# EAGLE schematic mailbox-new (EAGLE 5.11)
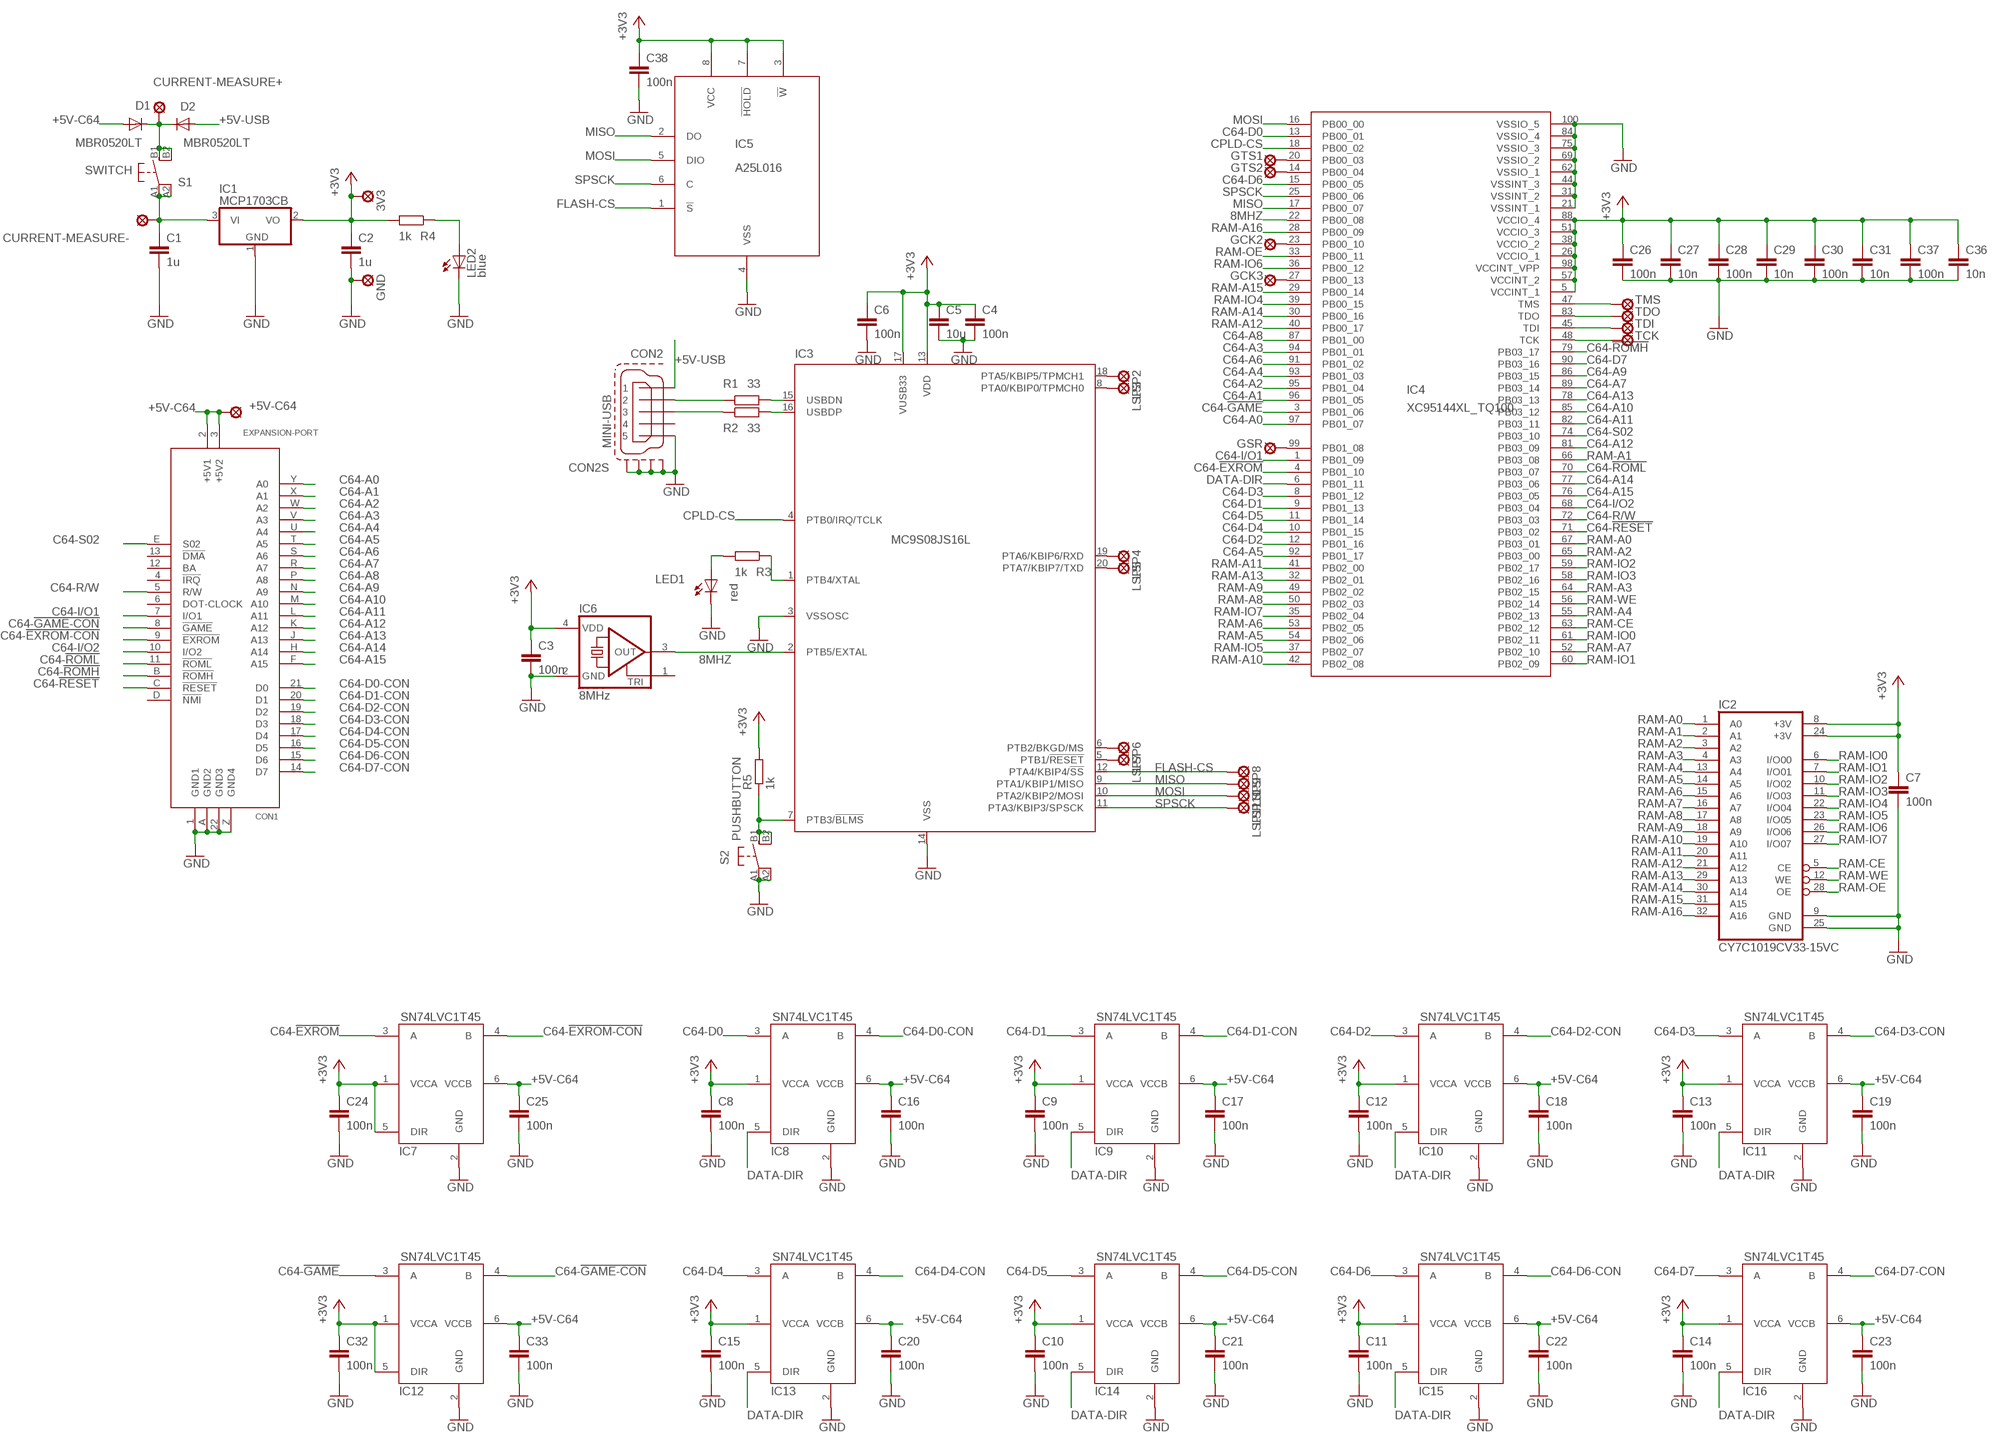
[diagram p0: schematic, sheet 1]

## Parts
3V3  LSP10  [LSP10]
+5V-C64  LSP10  [LSP10]
C1  1u  C-EUC1210  [C1210]
C2  1u  C-EUC1210  [C1210]
C3  100n  C-EUC0603  [C0603]
C4  100n  C-EUC0603  [C0603]
C5  10u  C-EUC1210  [C1210]
C6  100n  C-EUC0603  [C0603]
C7  100n  C-EUC0603  [C0603]
C8  100n  C-EUC0603  [C0603]
C9  100n  C-EUC0603  [C0603]
C10  100n  C-EUC0603  [C0603]
C11  100n  C-EUC0603  [C0603]
C12  100n  C-EUC0603  [C0603]
C13  100n  C-EUC0603  [C0603]
C14  100n  C-EUC0603  [C0603]
C15  100n  C-EUC0603  [C0603]
C16  100n  C-EUC0603  [C0603]
C17  100n  C-EUC0603  [C0603]
C18  100n  C-EUC0603  [C0603]
C19  100n  C-EUC0603  [C0603]
C20  100n  C-EUC0603  [C0603]
C21  100n  C-EUC0603  [C0603]
C22  100n  C-EUC0603  [C0603]
C23  100n  C-EUC0603  [C0603]
C24  100n  C-EUC0603  [C0603]
C25  100n  C-EUC0603  [C0603]
C26  100n  C-EUC0603  [C0603]
C27  10n  C-EUC0603  [C0603]
C28  100n  C-EUC0603  [C0603]
C29  10n  C-EUC0603  [C0603]
C30  100n  C-EUC0603  [C0603]
C31  10n  C-EUC0603  [C0603]
C32  100n  C-EUC0603  [C0603]
C33  100n  C-EUC0603  [C0603]
C36  10n  C-EUC0603  [C0603]
C37  100n  C-EUC0603  [C0603]
C38  100n  C-EUC0603  [C0603]
CON1  EXPANSION-PORT  [EXPANSION-PORT]
CON2  MINI-USB  MINI-USB-SHIELD-UX60-MB-5ST  [TYCO]
CURRENT-MEASURE+  LSP10  [LSP10]
CURRENT-MEASURE-  LSP10  [LSP10]
D1  MBR0520LT  [SOD123]
D2  MBR0520LT  [SOD123]
GCK2  LSP10  [LSP10]
GCK3  LSP10  [LSP10]
GND  LSP10  [LSP10]
GSR  LSP10  [LSP10]
GTS1  LSP10  [LSP10]
GTS2  LSP10  [LSP10]
IC1  MCP1703CB  [SOT23]
IC2  CY7C1019CV33-15VC  [SOJ32-400]
IC3  MC9S08JS16L  [SO-20DW]
IC4  XC95144XL_TQ100  XC9572XL_TQ100  [TQ100]
IC5  A25L016  [SOIC8]
IC6  8MHz  ASE  [ASE]
IC7  SN74LVC1T45  [SOT23-6]
IC8  SN74LVC1T45  [SOT23-6]
IC9  SN74LVC1T45  [SOT23-6]
IC10  SN74LVC1T45  [SOT23-6]
IC11  SN74LVC1T45  [SOT23-6]
IC12  SN74LVC1T45  [SOT23-6]
IC13  SN74LVC1T45  [SOT23-6]
IC14  SN74LVC1T45  [SOT23-6]
IC15  SN74LVC1T45  [SOT23-6]
IC16  SN74LVC1T45  [SOT23-6]
LED1  red  LED5MM  [LED5MM]
LED2  blue  LED5MM  [LED5MM]
LSP2  LSP10  [LSP10]
LSP3  LSP10  [LSP10]
LSP4  LSP10  [LSP10]
LSP5  LSP10  [LSP10]
LSP6  LSP10  [LSP10]
LSP7  LSP10  [LSP10]
LSP8  LSP10  [LSP10]
LSP9  LSP10  [LSP10]
LSP10  LSP10  [LSP10]
LSP11  LSP10  [LSP10]
R1  33  R-EU_R0805  [R0805]
R2  33  R-EU_R0805  [R0805]
R3  1k  R-EU_R0805  [R0805]
R4  1k  R-EU_R0805  [R0805]
R5  1k  R-EU_R0805  [R0805]
S1  SWITCH  [SWITCH]
S2  PUSHBUTTON  [PUSHBUTTON]
TCK  LSP10  [LSP10]
TDI  LSP10  [LSP10]
TDO  LSP10  [LSP10]
TMS  LSP10  [LSP10]

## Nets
8MHZ: IC3.2(PTB5/EXTAL) IC4.22(PB00_08) IC6.3(OUT)
+3V3: 3V3.MP C2.1 C3.1 C4.1 C5.1 C6.1 C7.1 C8.1 C9.1 C10.1 C11.1 C12.1 C13.1 C14.1 C15.1 C24.1 C26.1 C27.1 C28.1 C29.1 C30.1 C31.1 C32.1 C36.1 C37.1 C38.1 IC1.2(VO) IC2.8(+3V) IC2.24(+3V) IC3.13(VDD) IC3.17(VUSB33) IC4.5(VCCINT_1) IC4.26(VCCIO_1) IC4.38(VCCIO_2) IC4.51(VCCIO_3) IC4.57(VCCINT_2) IC4.88(VCCIO_4) IC4.98(VCCINT_VPP) IC5.3(!W) IC5.7(!HOLD) IC5.8(VCC) IC6.4(VDD) IC7.1(VCCA) IC7.5(DIR) IC8.1(VCCA) IC9.1(VCCA) IC10.1(VCCA) IC11.1(VCCA) IC12.1(VCCA) IC12.5(DIR) IC13.1(VCCA) IC14.1(VCCA) IC15.1(VCCA) IC16.1(VCCA) R4.2 R5.2
+5V-C64: +5V-C64.MP C16.1 C17.1 C18.1 C19.1 C20.1 C21.1 C22.1 C23.1 C25.1 C33.1 CON1.2(+5V1) CON1.3(+5V2) D1.A IC7.6(VCCB) IC8.6(VCCB) IC9.6(VCCB) IC10.6(VCCB) IC11.6(VCCB) IC12.6(VCCB) IC13.6(VCCB) IC14.6(VCCB) IC15.6(VCCB) IC16.6(VCCB)
+5V-USB: CON2.1 D2.A
C64-!EXROM: IC4.4(PB01_10) IC7.3(A)
C64-!EXROM-CON: CON1.9(!EXROM) IC7.4(B)
C64-!GAME: IC4.3(PB01_06) IC12.3(A)
C64-!GAME-CON: CON1.8(!GAME) IC12.4(B)
C64-!RESET: CON1.C(!RESET) IC4.71(PB03_02)
C64-!ROMH: CON1.B(!ROMH) IC4.79(PB03_17)
C64-!ROML: CON1.11(!ROML) IC4.70(PB03_07)
C64-A0: CON1.Y(A0) IC4.97(PB01_07)
C64-A1: CON1.X(A1) IC4.96(PB01_05)
C64-A2: CON1.W(A2) IC4.95(PB01_04)
C64-A3: CON1.V(A3) IC4.94(PB01_01)
C64-A4: CON1.U(A4) IC4.93(PB01_03)
C64-A5: CON1.T(A5) IC4.92(PB01_17)
C64-A6: CON1.S(A6) IC4.91(PB01_02)
C64-A7: CON1.R(A7) IC4.89(PB03_14)
C64-A8: CON1.P(A8) IC4.87(PB01_00)
C64-A9: CON1.N(A9) IC4.86(PB03_15)
C64-A10: CON1.M(A10) IC4.85(PB03_12)
C64-A11: CON1.L(A11) IC4.82(PB03_11)
C64-A12: CON1.K(A12) IC4.81(PB03_09)
C64-A13: CON1.J(A13) IC4.78(PB03_13)
C64-A14: CON1.H(A14) IC4.77(PB03_06)
C64-A15: CON1.F(A15) IC4.76(PB03_05)
C64-D0: IC4.13(PB00_01) IC8.3(A)
C64-D0-CON: CON1.21(D0) IC8.4(B)
C64-D1: IC4.9(PB01_13) IC9.3(A)
C64-D1-CON: CON1.20(D1) IC9.4(B)
C64-D2: IC4.12(PB01_16) IC10.3(A)
C64-D2-CON: CON1.19(D2) IC10.4(B)
C64-D3: IC4.8(PB01_12) IC11.3(A)
C64-D3-CON: CON1.18(D3) IC11.4(B)
C64-D4: IC4.10(PB01_15) IC13.3(A)
C64-D4-CON: CON1.17(D4) IC13.4(B)
C64-D5: IC4.11(PB01_14) IC14.3(A)
C64-D5-CON: CON1.16(D5) IC14.4(B)
C64-D6: IC4.15(PB00_05) IC15.3(A)
C64-D6-CON: CON1.15(D6) IC15.4(B)
C64-D7: IC4.90(PB03_16) IC16.3(A)
C64-D7-CON: CON1.14(D7) IC16.4(B)
C64-I/O1: CON1.7(I/O1) IC4.1(PB01_09)
C64-I/O2: CON1.10(I/O2) IC4.68(PB03_04)
C64-R/W: CON1.5(R/W) IC4.72(PB03_03)
C64-S02: CON1.E(S02) IC4.74(PB03_10)
CPLD-CS: IC3.4(PTB0/IRQ/TCLK) IC4.18(PB00_02)
DATA-DIR: IC4.6(PB01_11) IC8.5(DIR) IC9.5(DIR) IC10.5(DIR) IC11.5(DIR) IC13.5(DIR) IC14.5(DIR) IC15.5(DIR) IC16.5(DIR)
FLASH-CS: IC3.12(PTA4/KBIP4/!SS) IC5.1(!S) LSP8.MP
GND: C1.2 C2.2 C3.2 C4.2 C5.2 C6.2 C7.2 C8.2 C9.2 C10.2 C11.2 C12.2 C13.2 C14.2 C15.2 C16.2 C17.2 C18.2 C19.2 C20.2 C21.2 C22.2 C23.2 C24.2 C25.2 C26.2 C27.2 C28.2 C29.2 C30.2 C31.2 C32.2 C33.2 C36.2 C37.2 C38.2 CON1.1(GND1) CON1.22(GND3) CON1.A(GND2) CON1.Z(GND4) CON2.5 CON2.M1(S1) CON2.M2(S2) CON2.M3(S3) CON2.M4(S4) GND.MP IC1.1(GND) IC2.9(GND) IC2.25(GND) IC3.3(VSSOSC) IC3.14(VSS) IC4.21(VSSINT_1) IC4.31(VSSINT_2) IC4.44(VSSINT_3) IC4.62(VSSIO_1) IC4.69(VSSIO_2) IC4.75(VSSIO_3) IC4.84(VSSIO_4) IC4.100(VSSIO_5) IC5.4(VSS) IC6.2(GND) IC7.2(GND) IC8.2(GND) IC9.2(GND) IC10.2(GND) IC11.2(GND) IC12.2(GND) IC13.2(GND) IC14.2(GND) IC15.2(GND) IC16.2(GND) LED1.K(C) LED2.K(C) S2.A1(P) S2.A2(P1)
MISO: IC3.9(PTA1/KBIP1/MISO) IC4.17(PB00_07) IC5.2(DO) LSP9.MP
MOSI: IC3.10(PTA2/KBIP2/MOSI) IC4.16(PB00_00) IC5.5(DIO) LSP10.MP
N$1: CON2.2 R1.1
N$3: IC3.1(PTB4/XTAL) R3.1
N$4: LED2.A R4.1
N$5: C1.1 CURRENT-MEASURE-.MP IC1.3(VI) S1.A1(P) S1.A2(P1)
N$6: CON2.3 R2.1
N$7: IC3.15(USBDN) R1.2
N$8: IC3.16(USBDP) R2.2
N$9: LED1.A R3.2
N$10: CURRENT-MEASURE+.MP D1.C D2.C S1.B1(S) S1.B2(S1)
N$11: IC3.18(PTA5/KBIP5/TPMCH1) LSP2.MP
N$12: IC3.8(PTA0/KBIP0/TPMCH0) LSP3.MP
N$13: IC3.19(PTA6/KBIP6/RXD) LSP4.MP
N$14: IC3.20(PTA7/KBIP7/TXD) LSP5.MP
N$15: IC3.6(PTB2/BKGD/MS) LSP6.MP
N$16: IC3.5(PTB1/!RESET) LSP7.MP
N$18: GCK2.MP IC4.23(PB00_10)
N$19: GCK3.MP IC4.27(PB00_13)
N$20: GTS1.MP IC4.20(PB00_03)
N$21: GTS2.MP IC4.14(PB00_04)
N$22: GSR.MP IC4.99(PB01_08)
N$35: IC3.7(PTB3/!BLMS) R5.1 S2.B1(S) S2.B2(S1)
RAM-A0: IC2.1(A0) IC4.67(PB03_01)
RAM-A1: IC2.2(A1) IC4.66(PB03_08)
RAM-A2: IC2.3(A2) IC4.65(PB03_00)
RAM-A3: IC2.4(A3) IC4.64(PB02_15)
RAM-A4: IC2.13(A4) IC4.55(PB02_13)
RAM-A5: IC2.14(A5) IC4.54(PB02_06)
RAM-A6: IC2.15(A6) IC4.53(PB02_05)
RAM-A7: IC2.16(A7) IC4.52(PB02_10)
RAM-A8: IC2.17(A8) IC4.50(PB02_03)
RAM-A9: IC2.18(A9) IC4.49(PB02_02)
RAM-A10: IC2.19(A10) IC4.42(PB02_08)
RAM-A11: IC2.20(A11) IC4.41(PB02_00)
RAM-A12: IC2.21(A12) IC4.40(PB00_17)
RAM-A13: IC2.29(A13) IC4.32(PB02_01)
RAM-A14: IC2.30(A14) IC4.30(PB00_16)
RAM-A15: IC2.31(A15) IC4.29(PB00_14)
RAM-A16: IC2.32(A16) IC4.28(PB00_09)
RAM-CE: IC2.5(CE) IC4.63(PB02_12)
RAM-IO0: IC2.6(I/O00) IC4.61(PB02_11)
RAM-IO1: IC2.7(I/O01) IC4.60(PB02_09)
RAM-IO2: IC2.10(I/O02) IC4.59(PB02_17)
RAM-IO3: IC2.11(I/O03) IC4.58(PB02_16)
RAM-IO4: IC2.22(I/O04) IC4.39(PB00_15)
RAM-IO5: IC2.23(I/O05) IC4.37(PB02_07)
RAM-IO6: IC2.26(I/O06) IC4.36(PB00_12)
RAM-IO7: IC2.27(I/O07) IC4.35(PB02_04)
RAM-OE: IC2.28(OE) IC4.33(PB00_11)
RAM-WE: IC2.12(WE) IC4.56(PB02_14)
SPSCK: IC3.11(PTA3/KBIP3/SPSCK) IC4.25(PB00_06) IC5.6(C) LSP11.MP
TCK: IC4.48(TCK) TCK.MP
TDI: IC4.45(TDI) TDI.MP
TDO: IC4.83(TDO) TDO.MP
TMS: IC4.47(TMS) TMS.MP
Unconnected: CON1.4(!IRQ) CON1.6(DOT-CLOCK) CON1.12(BA) CON1.13(!DMA) CON1.D(!NMI) CON2.4 IC6.1(TRI)

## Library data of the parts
3V3 +5V-C64 CURRENT-MEASURE+ CURRENT-MEASURE- GCK2 GCK3 GND GSR GTS1 GTS2 LSP2-LSP11 TCK TDI TDO TMS = solpad:LSP10: SOLDER PAD
C1-C33 C36-C38 = rcl:C-EU: CAPACITOR, European symbol
CON1 = cartridge:EXPANSION-PORT
CON2 = cartridge:MINI-USB-SHIELD-: MINI USB Connector Source: http://www.hirose.co.jp/cataloge_hp/e24000019.pdf; OC_FARNELL: unknown; OC_NEWARK: unknown
D1 D2 = diode:MBR0520LT: SCHOTTKY BARRIER RECTIFIER
IC1 = linear:MCP1703: 250 mA, 16V, Low Quiescent Current LDO Regulator Source: http://ww1.microchip.com/downloads/en/DeviceDoc/22049b.pdf
IC2 = memory-sram:CY7C1019CV33: 128K x 8 Static RAM 10ns Source: Cypress CYP05780611.pdf
IC3 = cartridge:MC9S08JS16L
IC4 = xc9572xl-tq100:XC9572XL_TQ100
IC5 = cartridge:A25L016
IC6 = cartridge:ASE: 3.3Vdc CMOS SMD CRYSTAL CLOCK OSCILLATOR SOurce: www.abracon.com; OC_FARNELL: unknown; OC_NEWARK: unknown
IC7-IC16 = cartridge:SN74LVC1T45
LED1 LED2 = led:LED: LED
R1-R5 = rcl:R-EU_: RESISTOR, European symbol
S1 = cartridge:SWITCH
S2 = cartridge:PUSHBUTTON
